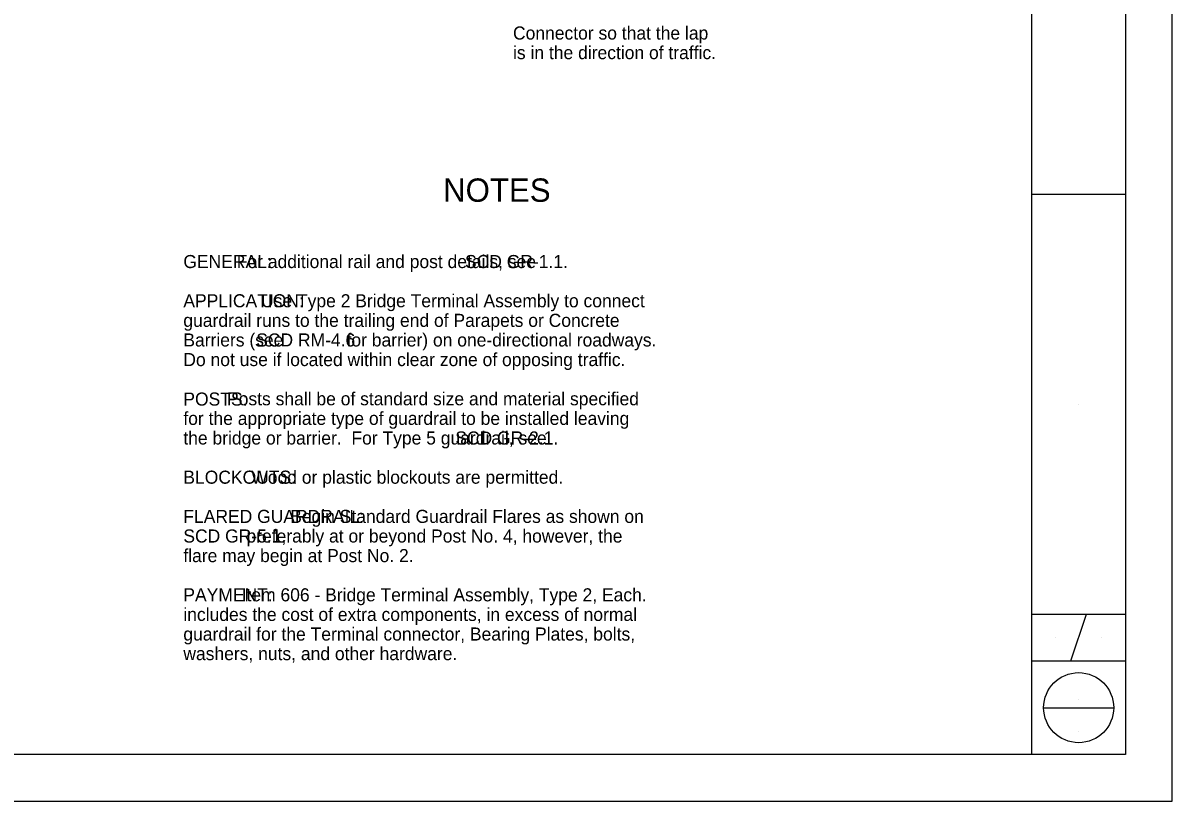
# Model space of a CAD drawing. Extents: x 0 to 34, y 0 to 22.
# Drawn here: x 21.69 to 34, y 0 to 8.33 of the extents above; entities that cross this region are included whole.
import ezdxf

# ---------------------------------------------------------------- set-up
doc = ezdxf.new("R2010")
doc.units = 0
for name, color, linetype in [('SH_Border', 7, 'Continuous'), ('SH_Cut_Line', 7, 'Continuous'), ('SH_Data', 7, 'Continuous'), ('ST_Text', 7, 'Continuous')]:
    doc.layers.add(name, color=color, linetype=linetype)

msp = doc.modelspace()

# ---------------------------------------------------------------- linework, layer by layer
at = {"layer": 'SH_Border'}
for p, q in [((32.5, 0.5), (32.5, 21.5)), ((32.5, 6.5), (33.5, 6.5)), ((32.5, 2), (33.5, 2)), ((32.917, 1.5), (33.083, 2)), ((32.5, 1.5), (33.5, 1.5))]:
    msp.add_line(p, q, dxfattribs=at)
msp.add_lwpolyline([(2, 21.5), (33.5, 21.5), (33.5, 0.5), (2, 0.5)], close=True, dxfattribs=at)
at = {"layer": 'SH_Cut_Line'}
msp.add_lwpolyline([(0, 0), (34, 0), (34, 22), (0, 22)], close=True, dxfattribs=at)
at = {"layer": 'SH_Data'}
for p, q in [((33, 4.25), (33, 4.25)), ((32.75, 1.75), (32.75, 1.75)), ((33.25, 1.75), (33.25, 1.75)), ((32.625, 1), (33.375, 1)), ((33, 1.085), (33, 1.085)), ((33, 0.745), (33, 0.745))]:
    msp.add_line(p, q, dxfattribs=at)
msp.add_circle((33, 1), 0.375, dxfattribs=at)

# ---------------------------------------------------------------- texts
at = {"layer": 'ST_Text'}
for s, height, p in [('Connector so that the lap', 0.14, (26.941, 8.157)), ('is in the direction of traffic.', 0.14, (26.941, 7.947)), ('NOTES', 0.25, (26.192, 6.419)), ('GENERAL:', 0.14, (23.41, 5.709)), ('           For additional rail and post details, see           ', 0.14, (23.41, 5.709)), ('                                                          SCD GR-1.1.', 0.14, (23.41, 5.709)), ('APPLICATION:', 0.14, (23.41, 5.289)), ('                Use Type 2 Bridge Terminal Assembly to connect', 0.14, (23.41, 5.289)), ('guardrail runs to the trailing end of Parapets or Concrete', 0.14, (23.41, 5.079)), ('Barriers (see             for barrier) on one-directional roadways.', 0.14, (23.41, 4.869)), ('               SCD RM-4.6', 0.14, (23.41, 4.869)), ('Do not use if located within clear zone of opposing traffic.', 0.14, (23.41, 4.659)), ('POSTS:', 0.14, (23.41, 4.236)), ('         Posts shall be of standard size and material specified', 0.14, (23.41, 4.239)), ('for the appropriate type of guardrail to be installed leaving', 0.14, (23.41, 4.029)), ('the bridge or barrier.  For Type 5 guardrail, see', 0.14, (23.41, 3.819)), ('                                                        SCD GR-2.1.', 0.14, (23.41, 3.819)), ('BLOCKOUTS:', 0.14, (23.41, 3.399)), ('              Wood or plastic blockouts are permitted.', 0.14, (23.41, 3.399)), ('FLARED GUARDRAIL:                                     ', 0.14, (23.41, 2.979)), ('                      Begin Standard Guardrail Flares as shown on', 0.14, (23.41, 2.979)), ('SCD GR-5.1,', 0.14, (23.41, 2.769)), ('             preferably at or beyond Post No. 4, however, the', 0.14, (23.41, 2.769)), ('flare may begin at Post No. 2.', 0.14, (23.41, 2.559)), ('PAYMENT:', 0.14, (23.41, 2.139)), ('            Item 606 - Bridge Terminal Assembly, Type 2, Each.', 0.14, (23.41, 2.139)), ('includes the cost of extra components, in excess of normal', 0.14, (23.41, 1.929)), ('guardrail for the Terminal connector, Bearing Plates, bolts,', 0.14, (23.41, 1.719)), ('washers, nuts, and other hardware.', 0.14, (23.41, 1.509))]:
    msp.add_text(s, height=height, dxfattribs=at).set_placement(p)

doc.saveas('drawing.dxf')
